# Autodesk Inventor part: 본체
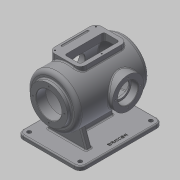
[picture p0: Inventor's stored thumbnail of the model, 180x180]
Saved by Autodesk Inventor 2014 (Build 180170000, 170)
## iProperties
Created: 2016-02
Part Number: 본체
Material: 일반
Document SubType Name: Modeling
Designer: mduedu
Density: 1 g/cm^3
Appearance: 기본값
Mass: 1387.61 g
Surface Area: 2685.54 cm^2
Volume: 1387.61 cm^3
Author: mduedu
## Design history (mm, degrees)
sketch "스케치2"
  geometry: L1 (0, 100)-(0, -100); L2 (65, -75.993)-(65, 100); L3 (65, 100)-(0, 100); A1 r 100 centre (0, 0) between (0, -100) and (65, -75.993); 2 further points
  constraints: 6 end point, 2 midpoint, 2 point on circle, 1 centre point, 1 coincident, 1 horizontal, 1 parallel, 1 vertical
  dimensions: "d3" = 200 distance of L1.start L1.end; "d5" = 130 diameter of L2 L1; "d6" = 100 radius of A1
revolve "회전1" sketch "스케치2" stored, may be unused: angle "d7" = 90 deg
sketch "스케치3"
  geometry: C1 r 47.5 at (0, 0); 1 further point
  constraints: 1 centre point, 1 coincident
  dimensions: "d8" = 95 diameter of C1
extrude "돌출2" join sketch "스케치3" distance "d10" = 10; taper "d11" = 0 deg
sketch "스케치5"
  geometry: L1 (47.5, 110)-(47.5, 100) reference; L2 (47.5, 100)-(65, 100) reference; L3 (65, 100)-(65, -75.993) reference; L4 (-65, -75.993)-(-65, 100) reference; L5 (-65, 100)-(-47.5, 100) reference; L6 (-47.5, 100)-(-47.5, 110) reference; L7 (-47.5, 110)-(47.5, 110) reference; L8 (55, 85)-(55, -71.239); L9 (0, 85)-(55, 85); L10 (0, 85)-(0, -90); A1 r 100 centre (0, 0) between (0, -100) and (65, -75.993) reference; A2 r 100 centre (0, 0) between (-65, -75.993) and (0, -100) reference; A3 r 90 centre (0, 0) between (0, -90) and (55, -71.239); 1 further point
  constraints: 6 end point, 2 point on circle, 1 centre point, 1 parallel, 1 perpendicular, 1 point on line, 1 vertical
  dimensions: "d13" = 10 distance between parallel lines of L3 L8; "d14" = 10 radial gap between concentric circles of A3 A1; "d15" = 15 distance between parallel lines of L9 L2
revolve "회전2" sketch "스케치5" stored, may be unused: angle "d16" = 90 deg
hole "구멍1" diameter "d19" = 65; stored, may be unused: countersink angle "d23" = 90 deg, drill point angle "d25" = 118 deg; dims "d17" = 10, "d18" = 10, "d20" = 6, "d21" = 4, "d22" = 2, "d24" = 8
node "작업 평면1"
sketch "스케치6"
  geometry: L1 (47.5, 110)-(-47.5, 110) reference; C1 r 40 at (0, -17); 1 further point
  constraints: 1 centre point, 1 vertical alignment
  dimensions: "d27" = 80 diameter of C1; "d29" = 127 distance from line of C1.centre L1
extrude "돌출3" join sketch "스케치6" stored distance "d30" = 10; taper "d31" = 0 deg
hole "구멍2" diameter "d34" = 42; stored, may be unused: countersink angle "d38" = 90 deg, drill point angle "d40" = 118 deg; dims "d32" = 10, "d33" = 10, "d35" = 6, "d36" = 52, "d37" = 18, "d39" = 8
sketch "스케치7" dims "d41" = 65
  geometry: C1 r 40 at (0, 0) reference; 3 further points
  constraints: 2 vertical alignment, 1 coincident, 2 other
hole "구멍3" sketch "스케치7" at (0, 32.5) diameter "d43" = 3.242; stored, may be unused: countersink angle "d47" = 90 deg, drill point angle "d49" = 118 deg; dims "d44" = 11, "d45" = 13, "d46" = 18, "d48" = 13
sketch "스케치8" dims "d53" = 80
  geometry: 3 further points
  constraints: 2 vertical alignment, 1 coincident, 2 other
hole "구멍4" sketch "스케치8" at (0, 40) diameter "d56" = 3.242; stored, may be unused: countersink angle "d60" = 90 deg, drill point angle "d62" = 118 deg; dims "d57" = 11, "d58" = 13, "d59" = 18, "d61" = 13
fillet "모깎기1" dims "d66" = 10
fillet "모깎기2" dims "d67" = 3
fillet "모깎기3" dims "d68" = 0.3
chamfer "모따기1" distance "d69" = 1; stored, may be unused: second distance "d70" = 2, angle "d71" = 45 deg
node "작업 평면5"
sketch "스케치10"
  geometry: L1 (-50, 0)-(50, 0); L2 (-50, 64)-(50, 64); L3 (50, 64)-(50, 50); L4 (50, 50)-(-50, 50); L5 (-50, 50)-(-50, 64); 3 further points
  constraints: 10 end point, 2 horizontal, 2 midpoint, 2 vertical, 1 coincident, 1 vertical alignment
  dimensions: "d132" = 100 distance of L1.start L1.end; "d158" = 50 distance between parallel lines of L4 L1; "d159" = 14 distance of L2.end L3.end; "d160" = 100 distance of L2.start L2.end
extrude "돌출5" join sketch "스케치10" stored distance "d84" = 10; taper "d85" = 0 deg
feature "면 기울기3" dims angle "d135" = 20 deg
sketch "스케치11"
  geometry: L1 (-100, 64)-(-100, 50) reference; L2 (-100, 50)-(-100, -50); L3 (-65, 90)-(-65, -71.239) reference; L4 (-100, -50)-(-65, -50); L5 (-100, 50)-(-55.515, 50) reference; 1 further point
  constraints: 4 end point, 1 collinear, 1 perpendicular, 1 point on line
  dimensions: "d161" = 100 distance between parallel lines of L4 L5
feature "리브1" sketch "스케치11" dims "d88" = 1, "d89" = 8, "d90" = 0, "d91" = 0, "d92" = 1, "d93" = 1
fillet "모깎기5" dims "d103" = 3
fillet "모깎기6" dims "d105" = 3
node "작업 평면6"
sketch "스케치15"
  geometry: L1 (-30, 60)-(50, 60); L2 (50, 60)-(50, -60); L3 (50, -60)-(-30, -60); L4 (-30, -60)-(-30, 60); 3 further points
  constraints: 8 end point, 2 parallel, 1 horizontal, 1 horizontal alignment, 1 midpoint, 1 perpendicular, 1 vertical alignment
  dimensions: "d110" = 80 distance of L2.end L3.end; "d112" = 60 distance from line of L3 point (10, 0); "d113" = 120 distance of L1.end L2.end; "d149" = 30 distance from line of L4 point (0, 0)
extrude "돌출8" join sketch "스케치15" stored distance "d114" = 10; taper "d115" = 0 deg
fillet "모깎기7" dims "d116" = 15
sketch "스케치16"
  geometry: L1 (-30, -45)-(-30, 45) reference; L2 (-15, 60)-(35, 60) reference; L3 (35, -60)-(-15, -60) reference; L4 (-20, -45)-(-20, 45); L5 (-15, 50)-(15, 50); L6 (20, 45)-(20, -45); L7 (15, -50)-(-15, -50); L8 (50, 45)-(50, -45) reference; A1 r 15 centre (-15, -45) between (-30, -45) and (-15, -60) reference; A2 r 15 centre (-15, 45) between (-15, 60) and (-30, 45) reference; A3 r 5 centre (-15, -45) between (-20, -45) and (-15, -50); A4 r 5 centre (-15, 45) between (-15, 50) and (-20, 45); A5 r 5 centre (15, 45) between (20, 45) and (15, 50); A6 r 5 centre (15, -45) between (15, -50) and (20, -45); A7 r 15 centre (35, 45) between (50, 45) and (35, 60) reference; A8 r 15 centre (35, -45) between (35, -60) and (50, -45) reference
  constraints: 8 end point, 8 point on circle, 4 centre point, 2 equal radius, 3 other
  dimensions: "d137" = 10 distance between parallel lines of L4 L1; "d150" = 40 distance between parallel lines of L6 L4; "d151" = 100 distance between parallel lines of L7 L5
extrude "돌출9" cut sketch "스케치16" stored distance "d118" = 10; taper "d119" = 0 deg
fillet "모깎기8" dims "d120" = 3
sketch "스케치17"
  geometry: L1 (-30, -45)-(-30, 45) reference; L2 (-20, 45)-(-20, -45) reference; L3 (-15, -50)-(15, -50) reference; L4 (20, -45)-(20, 45) reference; L5 (15, 50)-(-15, 50) reference; L6 (-15, 60)-(35, 60) reference; L7 (35, -60)-(-15, -60) reference; L8 (15, 55)-(-15, 55); L9 (-25, 45)-(-25, -45); L10 (-15, -55)-(15, -55); L11 (25, -45)-(25, 45); L12 (50, 45)-(50, -45) reference; L13 (35, 55)-(-15, 55); L14 (-25, 45)-(-25, -45); L15 (-15, -55)-(35, -55); L16 (45, -45)-(45, 45); A1 r 5 centre (-15, 45) between (-15, 50) and (-20, 45) reference; A2 r 5 centre (-15, -45) between (-20, -45) and (-15, -50) reference; A3 r 5 centre (15, -45) between (15, -50) and (20, -45) reference; A4 r 5 centre (15, 45) between (20, 45) and (15, 50) reference; A5 r 15 centre (-15, 45) between (-15, 60) and (-30, 45) reference; A6 r 15 centre (-15, -45) between (-30, -45) and (-15, -60) reference; A7 r 10 centre (-15, 45) between (-15, 55) and (-25, 45); A8 r 10 centre (-15, -45) between (-25, -45) and (-15, -55); A9 r 10 centre (15, -45) between (15, -55) and (25, -45); A10 r 10 centre (15, 45) between (25, 45) and (15, 55); A11 r 15 centre (35, 45) between (50, 45) and (35, 60) reference; A12 r 15 centre (35, -45) between (35, -60) and (50, -45) reference; A13 r 10 centre (-15, 45) between (-15, 55) and (-25, 45); A14 r 10 centre (-15, -45) between (-25, -45) and (-15, -55); A15 r 10 centre (35, -45) between (35, -55) and (45, -45); A16 r 10 centre (35, 45) between (45, 45) and (35, 55); 6 further points
  constraints: 18 point on circle, 16 end point, 8 centre point, 4 midpoint, 4 tangent, 11 other
  dimensions: "d138" = 5 distance between parallel lines of L8 L6; "d157" = 5 distance between parallel lines of L12 L16
hole "구멍5" sketch "스케치17" at (-25, 0), (42.071, 52.071), (42.071, -52.071) diameter "d122" = 3.242; stored, may be unused: countersink angle "d126" = 90 deg, drill point angle "d128" = 118 deg; dims "d123" = 9, "d124" = 13, "d125" = 18, "d127" = 11
sketch "스케치19"
  geometry: L1 (-50, 70)-(-35, 70) reference; L2 (-50, 42.603)-(-50, 70) reference; C1 r 2.5 at (-43, 70); 1 further point
  constraints: 1 centre point, 1 point on line
  dimensions: "d152" = 5 diameter of C1; "d153" = 7 distance from line of C1.centre L2
extrude "돌출11" cut sketch "스케치19" stored distance "d154" = 70; taper "d155" = 0 deg
fillet "모깎기11" dims "d156" = 2.5
sketch "스케치20"
  geometry: L1 (-80, 110)-(80, 110); L2 (80, 110)-(80, -100); L3 (80, -100)-(-80, -100); L4 (-80, -100)-(-80, 110); 2 further points
  constraints: 8 end point, 2 parallel, 1 horizontal, 1 midpoint, 1 perpendicular, 1 vertical alignment
  dimensions: "d162" = 160 distance of L1.start L1.end; "d164" = 210 distance of L1.end L2.end; "d165" = 110 distance from line of L1 point (0, 0)
extrude "돌출12" join sketch "스케치20" distance "d166" = 10; taper "d167" = 0 deg
fillet "모깎기12" dims "d168" = 15
fillet "모깎기13" dims "d169" = 3
fillet "모깎기14" dims "d170" = 3
sketch "스케치21"
  geometry: C1 r 5 at (-65, -95); C2 r 5 at (65, -95); C3 r 5 at (65, 85); C4 r 5 at (-65, 85); A1 r 15 centre (-65, -95) between (-80, -95) and (-65, -110) reference; A2 r 15 centre (-65, 85) between (-65, 100) and (-80, 85) reference; A3 r 15 centre (65, 85) between (80, 85) and (65, 100) reference; A4 r 15 centre (65, -95) between (65, -110) and (80, -95) reference; 1 further point
  constraints: 4 centre point, 4 coincident, 3 equal radius
  dimensions: "d171" = 10 diameter of C1
extrude "돌출13" cut sketch "스케치21" stored distance "d172" = 10; taper "d173" = 0 deg
sketch "스케치22"
  geometry: L1 (80, -95)-(80, 85) reference; 2 further points
  constraints: 1 horizontal alignment, 1 other
  dimensions: "d174" = 15 distance from line of L1 point (65, 0)
feature "엠보싱2" sketch "스케치22" dims "d13" = 10, "d175" = 0.5, "d176" = 0
node "솔리드2"
pattern_circular "원형 패턴1" dims angle "d51" = 360 deg
mirror "대칭1"
pattern_circular "원형 패턴2" dims angle "d64" = 360 deg
node "절단 모서리 투영1"
node "절단 모서리 투영2"
node "절단 모서리 투영3"
other parameters: "d26" = 75
